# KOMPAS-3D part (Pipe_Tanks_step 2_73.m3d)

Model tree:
1. X Axis
2. Y Axis
3. Z Axis  (labels: Pipe Dn 50; Bend 90 Dn 50)
     Òîëùèíà ñòåíêè 1 = 1

Referenced files in C:\Documents and Settings\kashirsky\Мои документы\Camtasia Studio\Pipelines3D\Tanks\: Tanks_step 4.a3d
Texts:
  Pipe Dn 50
  Steel ASTM A295
  Three Point Plane
  Plane at Angle
  Line and Point Plane
  Axis through Two Vertices
  Axis of Feature
  Axis of Conical Surface
  Axis through Edge
  Trim by Surface
  Trim by Sketch
  Feature with No History
  Intersection Axis of Two Planes
  Two Line Plane
  Line and Face Plane
  Bend by line
  Hole in sheet body
  Cut in sheet body
  Point in CM
  Linear Dimension from Line to Point
  Surface Finish Symbol
  Geometric Tolerance Symbol
  Leader #1
  Leader #2
  Leader #3
  Shape Deviations and Datum
  Node point number
  Mark of coordination axis
  Node point designation
  Mark/Reference designation with leader
  Mark/reference designation on line
  Mark/Reference designation without leader
  Bend 90 Dn 50
  Plane of section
